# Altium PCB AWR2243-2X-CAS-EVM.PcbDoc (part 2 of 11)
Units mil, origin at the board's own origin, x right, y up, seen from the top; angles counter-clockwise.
Board outline 5118.11 x 3937.01 mil, 8 copper layers (Layer 1 - Top Layer, Layer 2 - GND, Layer 3 - Signal (Sensitive), Layer 4 - GND / Signal, Layer 5 - Signal, Layer 6 - PWR / Signal, Layer 7 - GND, Layer 8 - Bottom Layer), stack 54.8 mil thick; 629 components, 407 nets, 2243 pads, 3950 vias.
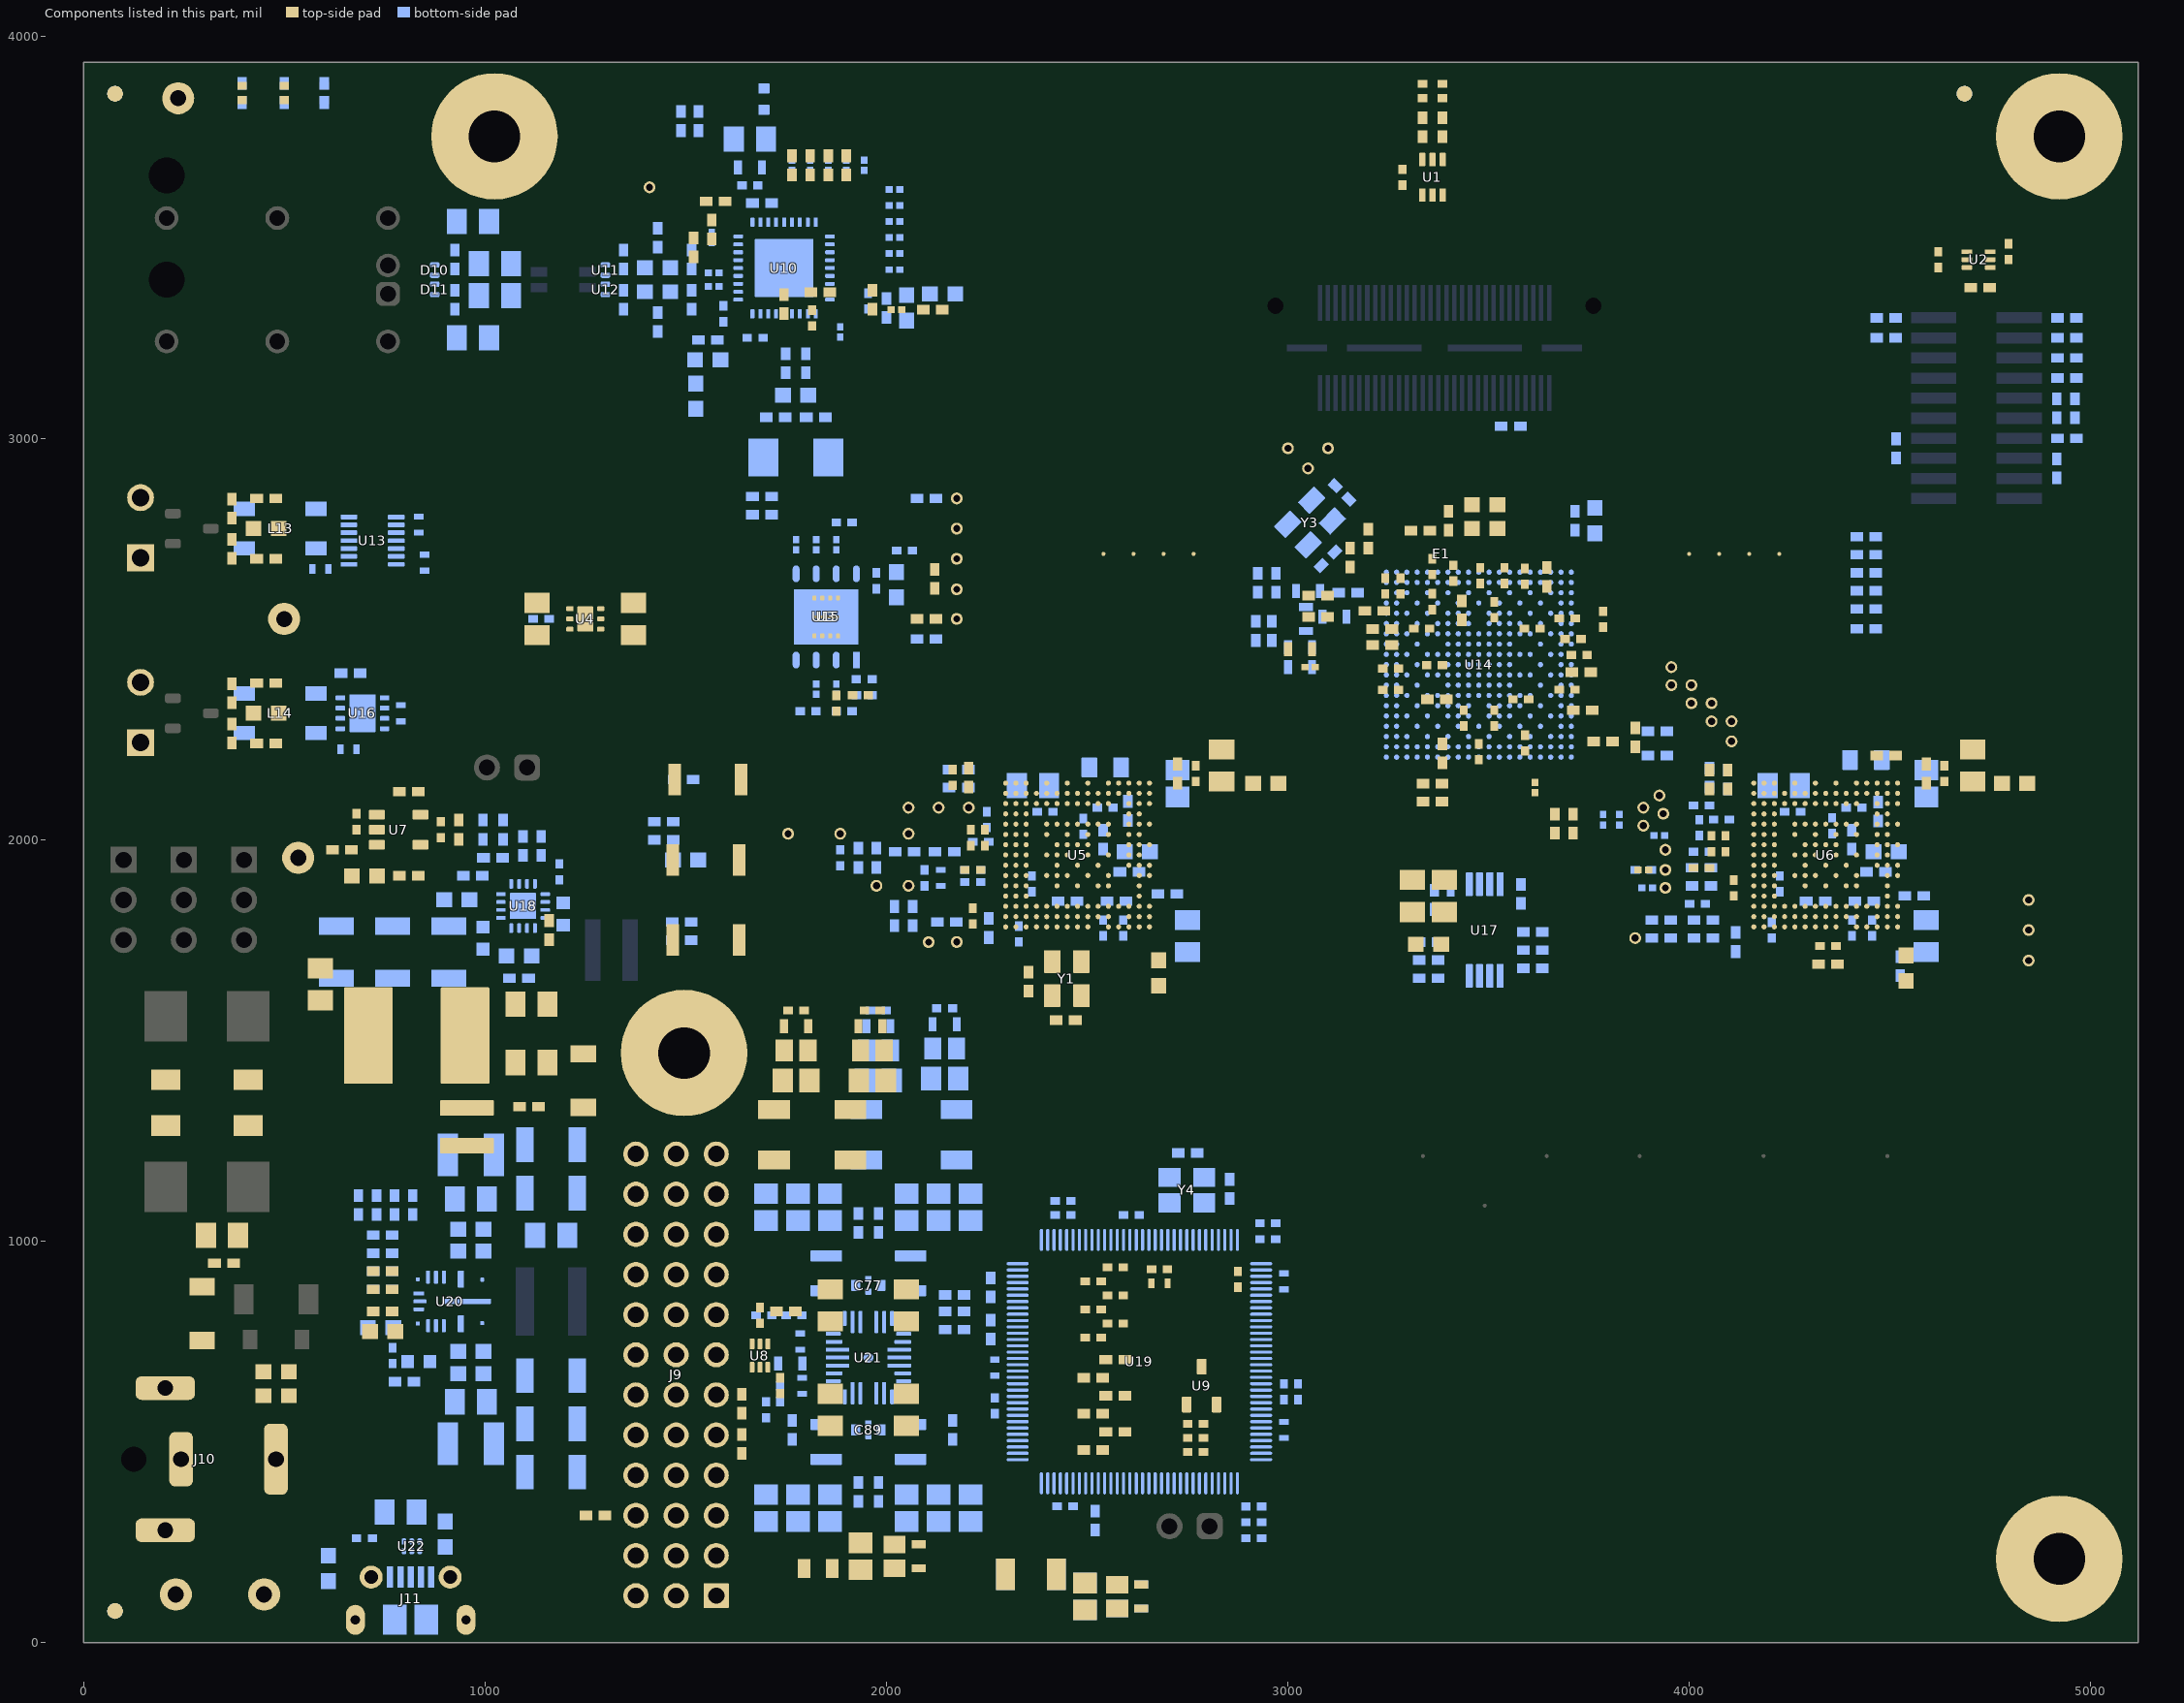
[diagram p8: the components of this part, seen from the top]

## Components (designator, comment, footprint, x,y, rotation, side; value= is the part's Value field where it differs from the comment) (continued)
R20 "CRCW040210K0JNED" 0402 3200,2750 r90 top value=10k
R21 "CRCW040210K0JNED" 0402 3330,2770 r180 top value=10k
R22 "CRCW040210K0JNED" 0402 3155,2703 r90 top value=10k
R23 "CRCW040261R9FKED" 0402 455,2700 r180 top value=61.9
R24 "CRCW040210K0FKED" 0402 3645,2655 r90 top value=10.0k
R25 "CRCW0402100KFKED" 0402 2120,2650 r90 top value=100k
R26 "CRCW040210K0DHEDP" 0402 3075,2608 r180 top value=10.0k
R27 "CRCW040210K0FKED" 0402 3215,2570 r0 top value=10.0k
R28 "CRCW040220K0FKED" 0402 3075,2555 r0 top value=20.0k
R29 "CRCW0402100KFKED" 0402 2100,2550 r180 top value=100k
R30 "CRCW040210K0FKED" 0402 3235,2525 r0 top value=10.0k
R31 "CRCW040210K0FKED" 0402 3235,2485 r180 top value=10.0k
R32 "CRCW02010000Z0ED" 0201 3055,2430 r180 top value=0
R33 "CRCW040261R9FKED" 0402 455,2390 r0 top value=61.9
R34 "CRCW040233R2FKED" 0402 3734.21,2322.69 r180 top value=33.2
R35 "CRCW040210K0FKED" 0402 3865,2255 r270 top value=10.0k
R36 "CRCW040210K0FKED" 0402 3785,2245 r0 top value=10.0k
R37 "CRCW040233R2FKED" 0402 3385,2215 r90 top value=33.2
R38 "CRCW040261R9FKED" 0402 455,2240 r180 top value=61.9
R39 "CRCW040249R9FKED" 0402 4490,2210 r180 top value=49.9
R40 "CRCW04020000Z0ED" 0402 2205,2155 r90 top value=0
R41 "CRCW04020000Z0ED" 0402 4050,2150 r90 top value=0
R42 "CRCW04022K94FKED" 0402 4095,2150 r90 top value=2.94k
R43 "CRCW04022K94FKED" 0402L 2165,2155 r90 top value=2.94k
R44 "MCT06030Z0000ZP500" 0603 2945,2140 r0 top value=0
R45 "MCT06030Z0000ZP500" 0603 4810,2140 r0 top value=0
R46 "CRCW040210K0JNED" 0402 3360,2140 r0 top value=10k
R47 "CRCW02010000Z0ED" 0201 3615,2130 r270 top value=0
R48 "CRCW040210K0JNED" 0402 3360,2095 r180 top value=10k
R49 "CRCW040210K0JNED" 0402 3665,2040 r270 top value=10k
R50 "CRCW040210K0JNED" 0402 3710,2040 r90 top value=10k
R51 "CRCW040224K9FKED" 0402 935,2025 r90 top value=24.9k
R52 "ERJ-2RKF1002X" 0402 644.25,1975 r0 top value=10.0k
R53 "CRCW040210K0FKED" 0402L 4030,1930 r180 top value=10.0k
R54 "CRCW02010000Z0ED" 0201 3885,1925 r0 top value=0
R55 "RFF" 0603 700,1910 r0 top value=1.00k
R56 "CRCW040210K0FKED" 0402L 2215,1925 r180 top value=10.0k
R57 "CRCW040260K4FKED" 0402 810,1910 r0 top value=60.4k
R58 "CRCW040210K0FKED" 0402 1160,1775 r90 top value=10.0k
R59 "CRCW040210K0FKED" 0402L 4345,1735 r0 top value=10.0k
R60 "CRCW04021R00FKED" 0402 1110,1335 r180 top value=1.00
R61 "CRCW04021R00FKED" 0402 350,945 r0 top value=1.00
R62 "CRCW040210K0FKED" 0402L 2570,935 r0 top value=10.0k
R63 "CRCW0402100KFKED" 0402 745,925 r180 top value=100k
R64 "ERJ-2GE0R00X" 0402L 2875,905 r90 top value=0
R65 "CRCW04021K00FKED" 0402L 2515,900 r180 top value=1.00k
R66 "CRCW040243K2FKED" 0402 745,880 r0 top value=43.2k
R67 "CRCW04021K00FKED" 0402L 2570,865 r180 top value=1.00k
R68 "CRCW04024K99FKED" 0402 745,825 r180 top value=4.99k
R69 "CRCW04021K00FKED" 0402L 2515,830 r0 top value=1.00k
R70 "CRCW04020000Z0ED" 0402 1750,825 r180 top value=0
R71 "CRCW04021K00FKED" 0402L 2570,795 r0 top value=1.00k
R72 "CRCW04024K87FKED" 0402L 2515,760 r180 top value=4.87k
R73 "CRCW040233R2FKED" 0402 2570,705 r180 top value=33.2
R74 "ERJ-2GE0R00X" 0402L 1735,640 r90 top value=10.0k
R75 "ERJ-2GE0R00X" 0402 2515,660 r180 top value=0
R76 "CRCW04022K94FKED" 0402 1640,595 r270 top value=2.94k
R77 "CRCW040233R2FKED" 0402 2570,615 r180 top value=33.2
R78 "CRCW040233R2FKED" 0402 2515,570 r180 top value=33.2
R79 "CRCW04021K00FKED" 0402L 2770,545 r0 top value=1.00k
R80 "ERJ-2GE0R00X" 0402 2570,525 r180 top value=0
R81 "CRCW04022K94FKED" 0402 1640,495 r90 top value=2.94k
R82 "ERJ-2GE0R00X" 0402 2515,480 r180 top value=0
R83 "CRCW04020000Z0ED" 0402 1275,316.5 r180 top value=0
R84 "ERJ-2RKF2200X" 0402 600,3860 r270 bottom value=220
R85 "ERJ-2RKF4700X" 0402 500,3860 r270 bottom value=470
R86 "ERJ-2RKF4700X" 0402 395,3860 r270 bottom value=470
R87 "CRCW04020000Z0ED" 0402 1531.77,3790 r270 bottom value=0
R88 "CRCW04020000Z0ED" 0402 1488,3790 r270 bottom value=0
R89 "CRCW020133R2FNED" 0201 1945,3680 r270 bottom value=33.2
R90 "CRCW020133R2FNED" 0201 1900,3680 r270 bottom value=33.2
R91 "CRCW020133R2FNED" 0201 1855,3680 r270 bottom value=33.2
R92 "CRCW020133R2FNED" 0201 1810,3680 r270 bottom value=33.2
R93 "CRCW020133R2FNED" 0201 1765,3680 r270 bottom value=33.2
R94 "CRCW020133R2FNED" 0201 2020,3620 r180 bottom value=33.2
R95 "CRCW020133R2FNED" 0201 2020,3580 r180 bottom value=33.2
R96 "CRCW0805100KJNEA" 0805_HV 970,3540 r180 bottom value=100k
R97 "CRCW020133R2FNED" 0201 2020,3540 r180 bottom value=33.2
R98 "CRCW020133R2FNED" 0201 1565,3500 r270 bottom value=33.2
R99 "CRCW020133R2FNED" 0201 2020,3500 r180 bottom value=33.2
R100 "CRCW040226R7FKED" 0402 1345,3445 r90 bottom value=26.7
R101 "CRCW04021K00FKED" 0402 925,3445 r270 bottom value=1.00k
R102 "CRCW020133R2FNED" 0201 2020,3460 r180 bottom value=33.2
R103 "RMCF0603ZT0R00" 0603 1430,3425 r180 bottom value=0
R104 "CRCW020133R2FNED" 0201 2020,3420 r180 bottom value=33.2
R105 "CRCW02010000Z0ED" 0201_Silk 1570,3412 r180 bottom value=0
R106 "CRCW040226R7FKED" 0402 1345,3345 r90 bottom value=26.7
R107 "CRCW04021K00FKED" 0402 925,3345 r90 bottom value=1.00k
R108 "RMCF0603ZT0R00" 0603 1430,3365 r180 bottom value=0
R109 "CRCW02010000Z0ED" 0201_Silk 1570,3378 r180 bottom value=0
R110 "CRCW04020000Z0ED" 0402 4940,3300 r0 bottom value=0
R111 "CRCW04024K70JNED" 0402 4490,3300 r0 bottom value=4.7k
R112 "CRCW020133R2FNED" 0201_Silk 1885,3265 r90 bottom value=33.2
R113 "CRCW04020000Z0ED" 0402 4940,3250 r0 bottom value=0
R114 "CRCW04020000Z0ED" 0402 4490,3250 r0 bottom value=0
R115 "CRCW04020000Z0ED" 0402 1799,3187 r90 bottom value=0
R116 "CRCW0402100RJNED" 0402 1749,3187 r270 bottom value=100
R117 "CRCW0402100RJNED" 0402 4940,3200 r0 bottom value=100
R118 "CRCW04020000Z0ED" 0402 4940,3150 r0 bottom value=0
R119 "CRCW06031M00FKEA" 0603 1774,3107 r0 bottom value=1.00Meg
R120 "CRCW04020000Z0ED" 0402 4960,3075 r90 bottom value=0
R121 "CRCW04020000Z0ED" 0402 4915,3075 r270 bottom value=0
R122 "CRCW040210K0JNED" 0402 3555,3030 r0 bottom value=10k
R123 "CRCW04024K70JNED" 0402 4515,2975 r270 bottom value=4.7k
R124 "CRCW04024K70JNED" 0402 4940,3000 r0 bottom value=4.7k
R125 "CRCW04020000Z0ED" 0402 4915,2925 r270 bottom value=0
R126 "CRCW04020000Z0ED" 0402 1690,2855 r180 bottom value=0
R127 "CRCW040210K0FKED" 0402 2100,2850 r180 bottom value=10.0k
R128 "CRCW040210K0FKED" 0402 3715,2795 r270 bottom value=10.0k
R129 "CRCW04020000Z0ED" 0402 1690,2810 r180 bottom value=0
R130 "CRCW040210K0FKED" 0402L 1895,2790 r0 bottom value=10.0k
R131 "CRCW040233R2FKED" 0402 4440,2755 r180 bottom value=33.2
R132 "CRCW020133R2FNED" 0201_Silk 1875,2735 r90 bottom value=33.2
R133 "CRCW020133R2FNED" 0201_Silk 1825,2735 r90 bottom value=33.2
R134 "CRCW020133R2FNED" 0201_Silk 1775,2735 r90 bottom value=33.2
R135 "ERJ-2GE0R00X" 0402L 2045,2720 r0 bottom value=0
R136 "CRCW040210K0FKED" 0402 4440,2710 r180 bottom value=10.0k
R137 "CRCW040220K0FKED" 0402 2970,2640 r270 bottom value=20.0k
R138 "CRCW040210K0DHEDP" 0402 2925,2640 r90 bottom value=10.0k
R139 "CRCW040233R2FKED" 0402 4440,2665 r180 bottom value=33.2
R140 "CRCW040233R2FKED" 0402 4440,2620 r180 bottom value=33.2
R141 "CRCW040210K0FKED" 0402 4440,2575 r0 bottom value=10.0k
R142 "CRCW04020000Z0ED" 0402 2960,2520 r270 bottom value=0
R143 "CRCW04020000Z0ED" 0402 2920,2520 r270 bottom value=0
R144 "CRCW040210K0FKED" 0402L 1140,2550 r0 bottom value=10.0k
R145 "CRCW040233R2FKED" 0402 4440,2525.58 r180 bottom value=33.2
R146 "CRCW040210K0JNED" 0402 2100,2500 r0 bottom value=10k
R147 "CRCW040210K0JNED" 0402 665,2415 r180 bottom value=10k
R148 "CRCW020133R2FNED" 0201_Silk 1875,2375 r90 bottom value=33.2
R149 "CRCW020133R2FNED" 0201_Silk 1825,2375 r90 bottom value=33.2
R150 "CRCW040247K5FKED" 0402L 1944.59,2400 r0 bottom value=47.5k
R151 "CRCW040210K0FKED" 0402L 1895,2320 r0 bottom value=10.0k
R152 "CRCW040210K0FKED" 0402L 1805,2320 r180 bottom value=10.0k
R153 "CRCW040233R2FKED" 0402 3920,2270 r180 bottom value=33.2
R154 "CRCW040233R2FKED" 0402 3920,2210 r180 bottom value=33.2
R155 "CRCW04022K94FKED" 0402 4095,2150 r90 bottom value=2.94k
R156 "CRCW04020000Z0ED" 0402 4050,2155 r90 bottom value=0
R157 "CRCW04022K94FKED" 0402 2180,2175 r180 bottom value=2.94k
R158 "CRCW04020000Z0ED" 0402 2180,2130 r180 bottom value=0
R159 "CRCW040210K0FKED" 0402L 4030,2085 r0 bottom value=10.0k
R160 "CRCW040210K0FKED" 0402L 2250,2050 r270 bottom value=10.0k
R161 "CRCW02010000Z0ED" 0201 3825,2050 r270 bottom value=0
R162 "CRCW02010000Z0ED" 0201 3785,2050 r270 bottom value=0
R163 "CRCW040233K0JNED" 0402 1445,2045 r180 bottom value=33k
R164 "CRCW040210K0FKED" 0402L 4025,2030 r90 bottom value=10.0k
R165 "CRCW040210K0FKED" 0402L 4080,2050 r180 bottom value=10.0k
R166 "CRCW040218K0FKED" 0402 1140,1985 r270 bottom value=18.0k
R167 "CRCW040210K0FKED" 0402 1095,1985 r270 bottom value=10.0k
R168 "CRCW02010000Z0ED" 0201 3925.23,2010.31 r0 bottom value=0
R169 "CRCW04023K30JNED" 0402 1445,2000 r180 bottom value=3.3k
R170 "CRCW040210K0FKED" 0402L 2235,1994.83 r180 bottom value=10.0k
R171 "CRCW040210K0JNED" 0402 1975,1955 r270 bottom value=10k
R172 "CRCW040210K0JNED" 0402 1930,1955 r90 bottom value=10k
R173 "CRCW040210K0JNED" 0402 2145,1970 r0 bottom value=10k
R174 "CRCW040210K0JNED" 0402 2045,1970 r0 bottom value=10k
R175 "CRCW040210K0FKED" 0402L 1885,1955 r270 bottom value=10.0k
R176 "CRCW040210K0FKED" 0402L 4030,1970 r0 bottom value=10.0k
R177 "CRCW040280K6FKED" 0402 1020,1955 r0 bottom value=80.6k
R178 "CRCW040210K0JNED" 0402 4030,1930 r180 bottom value=10k
R179 "CRCW040210K0FKED" 0402L 2095,1905 r270 bottom value=10.0k
R180 "CRCW040210K0FKED" 0402L 3885.23,1925 r180 bottom value=10.0k
R181 "CRCW040210K0FKED" 0402L 2215,1925 r180 bottom value=10.0k
R182 "CRCW04021K00FKED" 0402 970,1910 r180 bottom value=1.00k
R183 "CRCW040233R2FKED" 0402S 2135,1905 r270 bottom value=33.2
R184 "CRCW04020000Z0ED" 0402 3580,1865 r90 bottom value=0
R185 "CRCW040210K0FKED" 0402L 2215,1895 r0 bottom value=10.0k
R186 "CRCW040210K0JNED" 0402 4030,1885 r0 bottom value=10k
R187 "CRCW02010000Z0ED" 0201 3895,1880 r0 bottom value=0
R188 "CRCW040210K0JNED" 0402 2065,1810 r90 bottom value=10k
R189 "CRCW040210K0JNED" 0402 2020,1810 r270 bottom value=10k
R190 "CRCW040210K0FKED" 0402L 4020,1840 r0 bottom value=10.0k
R191 "CRCW040210K0JNED" 0402 4035,1800 r0 bottom value=10k
R192 "CRCW040210K0JNED" 0402 3930,1800 r180 bottom value=10k
R193 "CRCW04020000Z0ED" 0402 2150,1795 r180 bottom value=0
R194 "CRCW04022K49FKED" 0402 1490,1795 r180 bottom value=2.49k
R195 "CRCW04020000Z0ED" 0402 3610,1770 r180 bottom value=0
R196 "CRCW040210K0JNED" 0402 4035,1755 r180 bottom value=10k
R197 "CRCW040210K0JNED" 0402 3930,1755 r0 bottom value=10k
R198 "CRCW040249R9FKED" 0402 3350,1745 r0 bottom value=49.9
R199 "CRCW04020000Z0ED" 0402 3610,1725 r0 bottom value=0
R200 "CRCW040249R9FKED" 0402 4525,1685 r90 bottom value=49.9
R201 "CRCW04020000Z0ED" 0402 3350,1700 r180 bottom value=0
R202 "CRCW040210K0FKED" 0402 3610,1680 r0 bottom value=10.0k
R203 "CRCW04020000Z0ED" 0402 3350,1655 r180 bottom value=0
R204 "CRCW0402100KFKED" 0402 1085,1655 r0 bottom value=100k
R205 "CRCW04020000Z0ED" 0402 775,1090 r90 bottom value=0
R206 "CRCW04020000Z0ED" 0402 730,1090 r90 bottom value=0
R207 "CRCW04020000Z0ED" 0402 685,1090 r90 bottom value=0
R208 "CRCW04020000Z0ED" 0402 820,1090 r270 bottom value=0
R209 "CRCW04020000Z0ED" 0402 1980,1045 r90 bottom value=0
R210 "CRCW04020000Z0ED" 0402 1930,1045 r90 bottom value=0
R211 "CRCW040249R9FKED" 0402L 2440,1065 r0 bottom value=49.9
R212 "ERJ-2GEJ101X" 0402L 2950,1045 r0 bottom value=100
R213 "CRCW04020000Z0ED" 0402 745,1015 r0 bottom value=0
R214 "CRCW040228K0FKED" 0402 745,970 r0 bottom value=28.0k
R215 "CRCW040210K0FKED" 0402 745,925 r180 bottom value=10.0k
R216 "CRCW04020000Z0ED" 0402 2260,885 r90 bottom value=0
R217 "CRCW04026K81FKED" 0402 745,880 r0 bottom value=6.81k
R218 "CRCW04020000Z0ED" 0402 2170,825 r0 bottom value=0
R219 "CRCW04020000Z0ED" 0402 2260,780 r270 bottom value=0
R220 "CRCW04020000Z0ED" 0402L 1695,815 r180 bottom value=0
R221 "CRCW04020000Z0ED" 0402 2170,780 r0 bottom value=0
R222 "CRCW04020000Z0ED" 0402 800,650 r0 bottom value=0
R223 "CRCW04020000Z0ED" 0402L 1700,580 r270 bottom value=0
R224 "CRCW040210K0FKED" 0402 2165,530 r270 bottom value=10.0k
R225 "CRCW040210K0FKED" 0402 1765.21,530 r270 bottom value=10.0k
R226 "CRCW04020000Z0ED" 0402 1980,375 r270 bottom value=0
R227 "CRCW04020000Z0ED" 0402 1930,375 r270 bottom value=0
R228 "ERJ-2GE0R00X" 0402 2520,304.25 r90 bottom value=0
R229 "MCT06030Z0000ZP500" 0603 901,270 r90 bottom value=0
R230 "CRCW0402330KFKED" 0402L 2915,300 r180 bottom value=330k
R231 "CRCW0402330KFKED" 0402L 2915,260 r0 bottom value=330k
R232 "CRCW040230K0FKED" 0402L 700,260 r0 bottom value=30.0k
R233 "MCT06030Z0000ZP500" 0603 610,185 r90 bottom value=0
R234 "ERJ-2GE0R00X" 0402L 1945,2360 r0 bottom value=0
R235 "ERJ-2GE0R00X" 0402L 1935,2360 r0 top value=0
R236 "RMCF0603ZT0R00" 0603 2140,3360 r180 bottom value=0
R237 "RMCF0603ZT0R00" 0603 1525,3105 r90 bottom value=0
R238 "CRCW12060000Z0EAHP" 1206 410,1345 r90 top value=0
R239 "CRCW12060000Z0EAHP" 1206 205,1345 r90 top value=0
R240 "CRCW040247K5FKED" 0402L 1875,2340 r270 top value=47.5k
R241 "CRCW04021K00FKED" 0402 2170,866 r180 bottom value=1.00k
S1 "SKRKAEE010" SW_SKRKAEE010 1555,2150 r0 top
S2 "SKRKAEE010" SW_SKRKAEE010 1550,1950 r0 top
S3 "SKRKAEE010" SW_SKRKAEE010 1550,1750 r180 top
TP1 "5001" Keystone5001 235.98,3847.01 r90 top value=Black
TP2 "TP_H0.45P0.75" TP_H045P075 3000,2975 r90 top
TP3 "TP_H0.45P0.75" TP_H045P075 3100,2975 r90 top
TP4 "TP_H0.45P0.75" TP_H045P075 3050,2925 r90 top
TP5 "TP_H0.45P0.75" TP_H045P075 2175,2850 r90 top
TP6 "TP_H0.45P0.75" TP_H045P075 2175,2775 r90 top
TP7 "TP_H0.45P0.75" TP_H045P075 2175,2700 r90 top
TP8 "TP_H0.45P0.75" TP_H045P075 2175,2623.94 r90 top
TP9 "5000" Keystone5000 500,2550 r0 top value=Red
TP10 "TP_H0.45P0.75" TP_H045P075 2175,2550 r90 top
TP11 "TP_H0.45P0.75" TP_H045P075 3955,2430 r90 top
TP12 "TP_H0.45P0.75" TP_H045P075 3955,2385 r90 top
TP13 "TP_H0.45P0.75" TP_H045P075 4005,2385 r0 top
TP14 "TP_H0.45P0.75" TP_H045P075 4005,2340 r90 top
TP15 "TP_H0.45P0.75" TP_H045P075 4055,2340 r90 top
TP16 "TP_H0.45P0.75" TP_H045P075 4055,2295 r90 top
TP17 "TP_H0.45P0.75" TP_H045P075 4105,2295 r90 top
TP18 "TP_H0.45P0.75" TP_H045P075 4105,2245 r90 top
TP19 "TP_H0.45P0.75" TP_H045P075 3925.23,2110 r90 top
TP20 "TP_H0.45P0.75" TP_H045P075 2055,2080 r90 top
TP21 "TP_H0.45P0.75" TP_H045P075 2130,2080 r90 top
TP22 "TP_H0.45P0.75" TP_H045P075 2205,2080 r0 top
TP23 "TP_H0.45P0.75" TP_H045P075 3885.23,2080 r90 top
TP24 "TP_H0.45P0.75" TP_H045P075 3935,2064.76 r90 top
TP25 "TP_H0.45P0.75" TP_H045P075 3885.23,2035 r90 top
TP26 "TP_H0.45P0.75" TP_H045P075 1885,2015 r90 top
TP27 "TP_H0.45P0.75" TP_H045P075 2055,2015 r90 top
TP28 "5001" Keystone5001 535,1955 r90 top value=Black
TP29 "TP_H0.45P0.75" TP_H045P075 3940,1975 r90 top
TP30 "TP_H0.45P0.75" TP_H045P075 3940,1925 r90 top
TP31 "TP_H0.45P0.75" TP_H045P075 1975,1885.2 r90 top
TP32 "TP_H0.45P0.75" TP_H045P075 2055,1885.2 r90 top
TP33 "TP_H0.45P0.75" TP_H045P075 3940,1880 r90 top
TP34 "TP_H0.45P0.75" TP_H045P075 4845,1850 r90 top
TP35 "TP_H0.45P0.75" TP_H045P075 1755.13,2015 r90 top
TP36 "TP_H0.45P0.75" TP_H045P075 4845,1775 r90 top
TP37 "TP_H0.45P0.75" TP_H045P075 3865,1755 r90 top
TP38 "TP_H0.45P0.75" TP_H045P075 2175,1745.23 r90 top
TP39 "TP_H0.45P0.75" TP_H045P075 2105,1745 r90 top
TP40 "TP_H0.45P0.75" TP_H045P075 4845,1699.23 r90 top
TP41 "5001" Keystone5001 230,120 r90 top value=Black
TP42 "5000" Keystone5000 450,120 r90 top value=Red
TP43 "TP_H0.45P0.75" TP_H045P075 1410,3625 r90 top
U1 "SN74LVC2G17QDCKRQ1" DCK0006A_N 3360,3650 r90 top
U2 "TMP112AIDRLR" DRL0006A 4720,3445 r0 top
U3 "MX25V1635FZUS03" FP-MX25V1635FZUS03_USON8-MFG 1850,2555 r90 top
U4 "TPS7B8133QDRVRQ1" DRV0006A 1250,2550 r0 top
U5 "AWR2243ABGABLRQ1" ABL0161A 2475.98,1962.01 r270 top locked
U6 "AWR2243ABGABLRQ1" ABL0161A 4339.37,1962.01 r270 top locked
U7 "TPS78401QDBVQ1" DBV0005A_N 785,2025 r0 top
U8 "TMP112AIDRLR" DRL0006A 1685,715 r90 top
U9 "LM4040C25QDBZR" DBZ0003A_N 2785,640.28 r90 top
U10 "DP83TC812R-Q1" RHA0036A-MFG 1745,3424 r90 bottom
U11 "TPD1E10B06QDPYRQ1" DPY0002A 1300,3419 r270 bottom
U12 "TPD1E10B06QDPYRQ1" DPY0002A 1300,3371 r90 bottom
U13 "TCAN1043ADYYRQ1" DYY0014A-MFG 720,2745 r180 bottom
U14 "AM2732ADRFGQZCERQ1" ZCE0285A-MFG 3475.39,2436.14 r0 bottom locked
U15 "GD25Q64CW2G" FP-GD25Q64CW2G_WSON8-IPC_C 1850,2555 r90 bottom
U16 "TCAN1044VDRBTQ1" DRB0008J 695,2315 r180 bottom
U17 "LMK1C1102PWR" PW0008A-MFG 3490,1775 r90 bottom
U18 "TPS61379QRTE" RTE0016K-MFG 1095,1835 r180 bottom
U19 "TM4C1294NCPDTT3" PDT0128A 2630,700 r90 bottom locked
U20 "LM62460QRPHRQ1" RPH0016A 918.4,850 r90 bottom
U21 "LP876242B0RQKRQ1" RQK0032A-MFG 1955,710 r180 bottom
U22 "TPD4E004DRYR" DRY0006A 818,240 r90 bottom
Y1 "CX3225SA40000D0PTWCC" Kyocera_CX3225SA 2449.2,1654.12 r180 top
Y2 "ABM3-25.000MHZ-D2W-T" XTAL_ABM3 1774,2952 r180 bottom
Y3 "CX3225SA40000D0PTWCC" Kyocera_CX3225SA 3055,2790 r135 bottom
Y4 "NX3225SA-16.000M-STD-CRS-2" NDK_NX3225SA 2748.11,1127.01 r270 bottom
ZZ1 "This Assembly Note is for PCB labels only" AssemblyNoteLabel 225.98,4412.01 r0 top
ZZ2 "These assemblies are ESD sensitive, ESD precautions shall be observed." AssemblyNote 225.98,4312.01 r0 top
ZZ3 "These assemblies must be clean and free from flux and all contaminants. Use of no clean flux is not acceptable." AssemblyNote 225.98,4212.01 r0 top
ZZ4 "These assemblies must comply with workmanship standards IPC-A-610 Class 2, unless otherwise specified." AssemblyNote 225.98,4112.01 r0 top

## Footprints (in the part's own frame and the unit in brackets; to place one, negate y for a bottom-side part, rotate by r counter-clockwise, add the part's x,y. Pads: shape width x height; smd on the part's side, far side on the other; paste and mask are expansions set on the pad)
0201 [mm] "Data from Kemet datasheet CC101_COM dated 7/28/11"
  rect 0.46x0.42 smd mask+0.048: 1(-0.33,0) 2(0.33,0)
  body extent -0.31,-0.16 0.31,0.16, height 0.26
0201_Silk [mm] "Data from Kemet datasheet CC101_COM dated 7/28/11"
  rect 0.46x0.42 smd mask+0.048: 1(-0.33,0) 2(0.33,0)
  silkscreen extent -0.75,-0.4 0.75,0.4, body extent -0.31,-0.16 0.31,0.16, height 0.26
0402 [mm] "0402 from SM-752 data"
  rect 0.8x0.6 smd: 1(-0.6,0) 2(0.6,0)
  silkscreen extent -1.22,-0.52 1.22,0.52, body extent -0.55,-0.3 0.55,0.3, height 0.6
0402_065L [mm] "0402"
  rect 0.6x0.5 smd: 1(-0.5,0) 2(0.5,0)
  body extent -0.55,-0.3 0.55,0.3, height 0.65
0402_070 [mil] "SMD, 2-Leads, Body 1.2x0.7mm, Height 0.7mm"
  rect 15x24 smd: 1(-20,0) 2(20,0)
  body extent -24,-14 24,14, height 28
0402L [mm] "0402 from SM-752 data"
  rect 0.6x0.5 smd: 1(-0.5,0) 2(0.5,0)
  body extent -0.55,-0.3 0.55,0.3, height 0.6
0402S [mil] "Based on C0402S footprint from PADS legacy"
  rect 15x24 smd: 1(-20,0) 2(20,0)
  body extent -22,-12 22,12, height 24
0603 [mm] "0603 from SM-752 data"
  rect 1x0.95 smd: 1(-0.8,0) 2(0.8,0)
  silkscreen extent -1.52,-0.69 1.52,0.69, body extent -0.87,-0.47 0.87,0.47, height 1
0603L [mm] "0603 from SM-752 data"
  rect 0.8x0.85 smd: 1(-0.7,0) 2(0.7,0)
  silkscreen extent -0.07,-0.33 0.07,0.33, body extent -0.87,-0.47 0.87,0.47, height 1
0603S [mil]
  rect 20x35 smd: 1(-30,0) 2(30,0)
  body extent -34,-19 34,19, height 39
0805 [mm] "0805 from SM-752 data"
  rect 1.3x1.5 smd: 1(-0.85,0) 2(0.85,0)
  silkscreen extent -1.72,-0.97 1.72,0.97, body extent -1.1,-0.72 1.1,0.72, height 1.45
0805_HV [mil] "0805 with 30mil clearance between pads"
  rect 50x63 smd: 1(-40,0) 2(40,0)
  silkscreen extent -74,-40 74,40, body extent -43,-29 43,29, height 57
0805_HV1 [mm] "Custom footprint based on analyzing multiple manufacturer recommendations"
  rrect10% 1x1.25 smd: 1(-1,0) 2(1,0)
  silkscreen extent -0.2,-0.75 0.2,0.75, body extent -1.1,-0.72 1.1,0.73, height 1.45
0805L [mm] "0805 from SM-752 data"
  rect 1.1x1.4 smd: 1(-0.75,0) 2(0.75,0)
  body extent -1.1,-0.72 1.1,0.72, height 1.45
1206 [mm] "1206 from SM-752 data"
  rect 1.3x1.85 smd: 1(-1.45,0) 2(1.45,0)
  silkscreen extent -2.4,-1.21 2.4,1.21, body extent -1.7,-0.9 1.7,0.9, height 1.35
1206_180 [mm] "1206_180"
  rect 1.1x1.6 smd: 1(-1.7,0) 2(1.7,0)
  silkscreen extent -0.9,-1 0.9,1, body extent -1.75,-0.95 1.75,0.95, height 1.8
1210_270 [mm] "1210"
  rect 1.3x2.7 smd: 1(-1.45,0) 2(1.45,0)
  silkscreen extent -2.32,-1.57 2.32,1.57, body extent -1.7,-1.35 1.7,1.35, height 2.7
1210_280 [mm] "SMD, 2-Leads, Body 3.6x2.8mm, Height 2.8mm"
  rect 1.1x2.2 smd: 1(-1.65,0) 2(1.65,0)
  silkscreen extent -0.84,-1.4 0.84,1.4, body extent -1.8,-1.4 1.8,1.4, height 2.8
2220_390 [mm] "Laird recommended land pattern"
  rrect3% 3.07x6.1 smd: 1(-3.06,0) 2(3.06,0)
  silkscreen extent -1.3,-3 1.3,3, body extent -2.8,-2.54 2.79,2.54, height 3.9
ABL0161A [mm] "BGA, 161-Balls, Body 10.4x10.4mm, Pitch 0.65mm"
  round 0.32 smd mask+0.05: A1(-4.55,4.55) A2(-3.9,4.55) A3(-3.25,4.55) A5(-1.95,4.55) A7(-0.65,4.55) A9(0.65,4.55) A10(1.3,4.55) A13(3.25,4.55) A14(3.9,4.55) A15(4.55,4.55) B1(-4.55,3.9) B2(-3.9,3.9) B3(-3.25,3.9) B4(-2.6,3.9) B5(-1.95,3.9) B6(-1.3,3.9) B7(-0.65,3.9) B8(0,3.9) B9(0.65,3.9) B10(1.3,3.9) B11(1.95,3.9) B12(2.6,3.9) B13(3.25,3.9) B14(3.9,3.9) B15(4.55,3.9) C1(-4.55,3.25) C2(-3.9,3.25) C3(-3.25,3.25) C4(-2.6,3.25) C5(-1.95,3.25) C6(-1.3,3.25) C7(-0.65,3.25) C8(0,3.25) C9(0.65,3.25) C13(3.25,3.25) C14(3.9,3.25) C15(4.55,3.25) D1(-4.55,2.6) D2(-3.9,2.6) D13(3.25,2.6) D15(4.55,2.6) E1(-4.55,1.95) E2(-3.9,1.95) E3(-3.25,1.95) E5(-1.95,1.95) E6(-1.3,1.95) E8(0,1.95) E10(1.3,1.95) E11(1.95,1.95) E13(3.25,1.95) E14(3.9,1.95) E15(4.55,1.95) F2(-3.9,1.3) F3(-3.25,1.3) F5(-1.95,1.3) F9(0.65,1.3) F11(1.95,1.3) F13(3.25,1.3) F14(3.9,1.3) G1(-4.55,0.65) G2(-3.9,0.65) G3(-3.25,0.65) G5(-1.95,0.65) G6(-1.3,0.65) G7(-0.65,0.65) G8(0,0.65) G10(1.3,0.65) G13(3.25,0.65) G14(3.9,0.65) G15(4.55,0.65) H2(-3.9,0) H3(-3.25,0) H5(-1.95,0) H7(-0.65,0) H9(0.65,0) H11(1.95,0) H13(3.25,0) H14(3.9,0) H15(4.55,0) J1(-4.55,-0.65) J2(-3.9,-0.65) J3(-3.25,-0.65) J5(-1.95,-0.65) J6(-1.3,-0.65) J7(-0.65,-0.65) J8(0,-0.65) J10(1.3,-0.65) J13(3.25,-0.65) J14(3.9,-0.65) J15(4.55,-0.65) K2(-3.9,-1.3) K3(-3.25,-1.3) K5(-1.95,-1.3) K7(-0.65,-1.3) K8(0,-1.3) K9(0.65,-1.3) K10(1.3,-1.3) K11(1.95,-1.3) K13(3.25,-1.3) K14(3.9,-1.3) K15(4.55,-1.3) L1(-4.55,-1.95) L2(-3.9,-1.95) L3(-3.25,-1.95) L5(-1.95,-1.95) L6(-1.3,-1.95) L8(0,-1.95) L10(1.3,-1.95) L13(3.25,-1.95) L14(3.9,-1.95) L15(4.55,-1.95) M2(-3.9,-2.6) M3(-3.25,-2.6) M13(3.25,-2.6) M14(3.9,-2.6) M15(4.55,-2.6) N1(-4.55,-3.25) N2(-3.9,-3.25) N3(-3.25,-3.25) N4(-2.6,-3.25) N5(-1.95,-3.25) N6(-1.3,-3.25) N7(-0.65,-3.25) N8(0,-3.25) N9(0.65,-3.25) N10(1.3,-3.25) N11(1.95,-3.25) N12(2.6,-3.25) N13(3.25,-3.25) N14(3.9,-3.25) N15(4.55,-3.25) P1(-4.55,-3.9) P2(-3.9,-3.9) P3(-3.25,-3.9) P4(-2.6,-3.9) P5(-1.95,-3.9) P6(-1.3,-3.9) P7(-0.65,-3.9) P8(0,-3.9) P9(0.65,-3.9) P10(1.3,-3.9) P11(1.95,-3.9) P12(2.6,-3.9) P13(3.25,-3.9) P14(3.9,-3.9) P15(4.55,-3.9) R1(-4.55,-4.55) R2(-3.9,-4.55) R3(-3.25,-4.55) R4(-2.6,-4.55) R5(-1.95,-4.55) R6(-1.3,-4.55) R7(-0.65,-4.55) R8(0,-4.55) R9(0.65,-4.55) R10(1.3,-4.55) R11(1.95,-4.55) R12(2.6,-4.55) R13(3.25,-4.55) R14(3.9,-4.55) R15(4.55,-4.55)
  silkscreen extent -5.3,-5.3 5.3,5.3, body extent -5.2,-5.2 5.2,5.2, height 0.62
ACT45B [mm] "SMD, 4-Leads, Body 4.7 x 3.7 mm"
  rect 1.35x0.9 smd: 1(-2.275,1.25) 2(-2.275,-1.25) 3(2.275,-1.25) 4(2.275,1.25)
  silkscreen extent -2.35,-1.7 2.35,2, body extent -2.35,-1.7 2.35,1.7, height 3
AssemblyNote [mil] "Assembly Note"
AssemblyNoteLabel [mil] "Assembly Note for PCB Labels"
CE_Mark_5mm [mil] "Minimum text height for CE Mark"
  silkscreen extent -138,-98 138,98
CONN_105017-0001 [mm] "Molex Micro USB-B"
  rect 0.4x1.35 smd: 1(-1.3,1.35) 2(-0.65,1.35) 3(0,1.35) 4(0.65,1.35) 5(1.3,1.35)
  oval 1.2x1.9 hole 0.6 slot 1.3 at 90 deg: 6(-3.5,-1.35) 9(3.5,-1.35)
  rect 1.5x1.9 smd: 7(-1,-1.35) 8(1,-1.35)
  round 1.45 hole 0.85: 10(2.5,1.35) 11(-2.5,1.35)
  Layer 1 - Top Layer region: 3.5,-2.3 2.3,-2.3 2.3,-0.4 3.5,-0.4
  Layer 1 - Top Layer region: -3.5,-0.4 -2.3,-0.4 -2.3,-2.3 -3.5,-2.3
  silkscreen extent -4.1,-0.2 4.1,1.4, body extent -4.1,-3.93 4.1,1.5, height 2.72
CUI_PJ-063AH [mm] "DC POWER JACK, R/A, TH"
  rrect50% 1.5x4.5 hole 1 square: 1(-4.5,0)
  rrect50% 1.5x3.45 hole 1 square: 2(1.5,0)
  oval 1.35x1.3 hole 1.6 unplated mask+0.102: ALIGN(4.5,0)
  rrect50% 3.75x1.5 hole 1 square: S1(2.5,-4.5) S2(2.5,4.5)
  body extent -5.5,-5.15 7.5,5.15, height 9
DBV0005A_N [mm] "SOT23, 5-Leads, Body 2.9x1.6mm, Pitch 0.95mm, Lead Span 2.8mm, IPC Medium Density"
  rrect17% 1x0.6 smd: 1(-1.375,0.95) 2(-1.375,0) 3(-1.375,-0.95) 4(1.375,-0.95) 5(1.375,0.95)
  silkscreen extent -1.63,-1.55 0.38,1.55, body extent -1.42,-1.46 1.42,1.46, height 1.09
DBZ0003A_N [mm] "SOT23, 3-Leads, Body 2.9x1.3mm, Pitch 0.95mm, Lead Span 2.4mm, IPC Medium Density"
  rrect17% 1x0.6 smd: 1(-1.2,0.95) 2(-1.2,-0.95) 3(1.2,0)
  silkscreen extent 0.2,-1.5 0.7,1.5, body extent -1.26,-1.46 1.26,1.46, height 0.98
DCK0006A_N [mm] "SOT23, 6-Leads, Body 2x1.3mm, Pitch 0.65mm, Lead Span 2.1mm, IPC Medium Density"
  rrect25% 0.85x0.4 smd: 1(-1.125,0.65) 2(-1.125,0) 3(-1.125,-0.65) 4(1.125,-0.65) 5(1.125,0) 6(1.125,0.65)
  silkscreen extent -1.5,-1.09 0.51,1.09, body extent -1.14,-1 1.14,1, height 0.95
DPY0002A [mm] "X1SON-2"
  rrect57% 0.35x0.6 smd paste-0.5 mask-0.05: 1(-0.325,0) 2(0.325,0)
  rrect33% 0.3x0.5 on Bottom Paste: 1S(-0.35,0) 2S(0.35,0)
  silkscreen extent -0.38,-0.66 -0.33,-0.61, body extent -0.5,-0.3 0.5,0.3, height 0.45
DRB0008J [mm] "VSON-8"
  rrect33% 0.6x0.31 smd: 1(-1.4,0.975) 2(-1.4,0.325) 3(-1.4,-0.325) 4(-1.4,-0.975) 5(1.4,-0.975) 6(1.4,-0.325) 7(1.4,0.325) 8(1.4,0.975)
  rrect6% 1.65x2.4 smd paste-1.2: 9(0,0)
  silkscreen extent -1.73,-1.73 1.73,1.73, body extent -1.55,-1.55 1.55,1.55, height 1.01
DRL0006A [mm] "SOTFL, 6-Flat Leads, Body 1.2x1.6x0.6mm, Pitch 0.5mm, TI recommended"
  rrect33% 0.67x0.3 smd: 1(-0.74,0.5) 2(-0.74,0) 3(-0.74,-0.5) 4(0.74,-0.5) 5(0.74,0) 6(0.74,0.5)
  silkscreen extent -0.9,-0.95 0.5,0.95, body extent -0.8,-0.8 0.8,0.8, height 0.61
DRV0006A [mm] "SON, 6-Leads, Body 2x2mm, Pitch 0.65mm, Thermal Pad 1.6x1mm, TI Recommended"
  rrect33% 0.45x0.3 smd: 1(-0.975,0.65) 2(-0.975,0) 3(-0.975,-0.65) 4(0.975,-0.65) 5(0.975,0) 6(0.975,0.65)
  rrect14% 1x0.7 on Top Paste: 7(0,-0.45) 7(0,0.45)
  rrect10% 1x1.6 smd paste-0.5: 7(0,0)
  silkscreen extent -1.05,-1.2 1.05,1.2, body extent -1.05,-1.05 1.05,1.05, height 0.81
DRY0006A [mm] "USON-6"
  rrect67% 0.45x0.3 smd paste-0.05 mask-0.05: 1(-0.275,0.5)
  rrect67% 0.4x0.3 smd paste-0.05 mask-0.05: 2(-0.3,0) 3(-0.3,-0.5) 4(0.3,-0.5) 5(0.3,0) 6(0.3,0.5)
  body extent -0.5,-0.72 0.5,0.72, height 0.58
DYY0014A-MFG [mm]
  rrect33% 1.05x0.3 smd paste+0 mask+0: 1(-1.5,1.5) 2(-1.5,1) 3(-1.5,0.5) 4(-1.5,0) 5(-1.5,-0.5) 6(-1.5,-1) 7(-1.5,-1.5) 8(1.5,-1.5) 9(1.5,-1) 10(1.5,-0.5) 11(1.5,0) 12(1.5,0.5) 13(1.5,1) 14(1.5,1.5)
  silkscreen extent -1.9,-2.15 1.05,2.28, body extent -1.63,-2.1 1.63,2.1, height 1.1
ESD_Overlay_Small [mil]
  silkscreen extent -62,-48 64,61
FCC_disclaimer [mil]
Fiducial10-20 [mm]
  round 1 smd mask+0.5: 1(0,0)
FP-1902D_HEX_STANDOFF_#4-40-MFG [mil]
  round 128.5 hole 128.5 unplated paste-39370.1 mask+0: ""(0,0)
  body extent -125,-144 125,144, height 765
"FP-BLM18KG601SH1_0603 (1608 Metric)-MFG" [mm]
  rrect15% 0.65x0.7 smd paste+0 mask+0: 1(-0.675,0) 2(0.675,0)
  silkscreen extent -0.87,-0.75 0.87,0.75, body extent -0.8,-0.4 0.8,0.4, height 0.95
FP-GD25Q64CW2G_WSON8-IPC_C [mm]
  rrect23% 1.059x0.436 smd paste+0 mask+0: 1(-2.727,1.905)
  rrect100% 1.059x0.436 smd paste+0 mask+0: 2(-2.727,0.635) 3(-2.727,-0.635) 4(-2.727,-1.905) 5(2.727,-1.905) 6(2.727,-0.635) 7(2.727,0.635) 8(2.727,1.905)
  rrect3% 3.5x4.1 smd paste-1000 mask+0: 9(0,0)
  silkscreen extent -3,-2.5 3,3.17, body extent -3,-2.5 3,2.5, height 0.81
FP-MX25V1635FZUS03_USON8-MFG [mm]
  rrect40% 0.3x0.25 smd paste+0 mask+0: 1(-1.2,0.75) 2(-1.2,0.25) 3(-1.2,-0.25) 4(-1.2,-0.75) 5(1.2,-0.75) 6(1.2,-0.25) 7(1.2,0.25) 8(1.2,0.75)
  rrect50% 0.2x1.6 smd paste+0 mask+0: 9(0,0)
  silkscreen extent -2.12,-1.25 1.55,1.25, body extent -1.5,-1 1.5,1, height 0.6
FP-NFM18HC105C1C3D_0603-MFG [mm]
  rrect17% 0.6x0.7 smd paste+0 mask+0: 1(-0.8,0) 3(0.8,0)
  rrect25% 0.4x0.4 smd paste+0 mask+0: 2(0,-0.4) 2(0,0.4)
  silkscreen extent -1.27,-1.01 0.85,0.97, body extent -0.8,-0.4 0.8,0.4, height 0.7
FP-SSW-112-01-L-T_HDR36-MFG [mm]
  rrect6% 1.59x1.59 hole 1.04 paste-1000 mask+0: 1(13.97,-2.54)
  round 1.59 hole 1.04 paste-1000 mask+0: 2(13.97,0) 3(13.97,2.54) 4(11.43,-2.54) 5(11.43,0) 6(11.43,2.54) 7(8.89,-2.54) 8(8.89,0) 9(8.89,2.54) 10(6.35,-2.54) 11(6.35,0) 12(6.35,2.54) 13(3.81,-2.54) 14(3.81,0) 15(3.81,2.54) 16(1.27,-2.54) 17(1.27,0) 18(1.27,2.54) 19(-1.27,-2.54) 20(-1.27,0) 21(-1.27,2.54) 22(-3.81,-2.54) 23(-3.81,0) 24(-3.81,2.54) 25(-6.35,-2.54) 26(-6.35,0) 27(-6.35,2.54) 28(-8.89,-2.54) 29(-8.89,0) 30(-8.89,2.54) 31(-11.43,-2.54) 32(-11.43,0) 33(-11.43,2.54) 34(-13.97,-2.54) 35(-13.97,0) 36(-13.97,2.54)
  silkscreen extent -15.62,-4.59 15.62,3.81, body extent -15.49,-3.75 15.49,3.75, height 8.64
FP-TFM252012ALMAR47MTAA_1008-MFG [mm]
  rrect14% 0.7x2 smd paste+0 mask+0: 1(-1.1,0) 2(1.1,0)
  silkscreen extent -0.38,-1.1 0.38,1.1, body extent -1.25,-1 1.25,1, height 1.2
FP-XGL4030-102MEC_SMD_IND_4MM0_4MM0-MFG [mm]
  rrect10% 0.98x3.4 smd paste+0 mask+0: 1(-1.185,0) 2(1.185,0)
  silkscreen extent -2.15,-2.15 2.15,2.15, body extent -2.25,-2.25 2.25,2.25, height 0.25
IEC_HotSurface_Small [mil]
  silkscreen extent -107,-93 107,92
Keystone5000 [mil] "For Keystone 500x miniature loop terminals"
  round 80 hole 40: 1(0,0)
  silkscreen extent -52,-52 52,52, body extent -49,-49 49,49, height 182
Keystone5001 [mil] "For Keystone 500x miniature loop terminals"
  round 80 hole 40: 1(0,0)
  silkscreen extent -52,-52 52,52, body extent -49,-49 49,49, height 182
Kyocera_CX3225SA [mm] "SMD, 4-Leads, Body 3.2x2.5mm"
  rrect10% 1.05x1.45 smd: 1(-0.925,1.075) 2(-0.925,-1.075) 3(0.925,-1.075) 4(0.925,1.075)
  silkscreen extent -1.48,2.07 -1.36,2.2, body extent -1.3,-1.65 1.3,1.65, height 0.9
Label_650x200 [mil] "Thermal Transfer Label"
  round 1 on Mech13: 0(0,0)
  silkscreen extent -325,-100 325,100, body extent -325,-100 325,100, height 1
LED_SMLP12_ORANGE [mm] "Rohm Semiconductor"
  rect 0.5x0.6 smd mask+0.08: 1(-0.45,0) 2(0.45,0)
  silkscreen extent 0.92,-0.3 0.92,0.3, body extent -0.55,-0.35 0.55,0.35, height 0.25
LED_SMLP12_YELLOW [mm] "Rohm Semiconductor"
  rect 0.5x0.6 smd mask+0.08: 1(-0.45,0) 2(0.45,0)
  silkscreen extent 0.92,-0.3 0.92,0.3, body extent -0.55,-0.35 0.55,0.35, height 0.25
MPZ2012 [mm] "TDK"
  rect 0.8x1.2 smd: 1(-0.9,0) 2(0.9,0)
  body extent -1.1,-0.72 1.1,0.72, height 1.05
NDK_NX3225SA [mm] "NDK"
  rect 1.2x1.4 smd: 1(-0.8,1.1) 2(-0.8,-1.1) 3(0.8,-1.1) 4(0.8,1.1)
  body extent -1.3,-1.65 1.3,1.65, height 0.7
NLCV32 [mm] "TDK"
  rect 1.2x2 smd: 1(-1.6,0) 2(1.6,0)
  silkscreen extent -0.9,-1.4 0.9,1.4, body extent -1.7,-1.35 1.7,1.35, height 2.4
"NY PMS 440 0025 PH" [mm] "4-40 nylon screw and mounting hole"
  round 8 hole 3.2: 1(0,0)
  body extent -3.3,-3.3 3.3,3.3, height 2.69
PDT0128A [mm] "Thin QFP, 128-Leads, Body 14x14mm, Pitch 0.4mm"
  oval 1.4x0.2 smd: 1(-7.7,6.2) 2(-7.7,5.8) 3(-7.7,5.4) 4(-7.7,5) 5(-7.7,4.6) 6(-7.7,4.2) 7(-7.7,3.8) 8(-7.7,3.4) 9(-7.7,3) 10(-7.7,2.6) 11(-7.7,2.2) 12(-7.7,1.8) 13(-7.7,1.4) 14(-7.7,1) 15(-7.7,0.6) 16(-7.7,0.2) 17(-7.7,-0.2) 18(-7.7,-0.6) 19(-7.7,-1) 20(-7.7,-1.4) 21(-7.7,-1.8) 22(-7.7,-2.2) 23(-7.7,-2.6) 24(-7.7,-3) 25(-7.7,-3.4) 26(-7.7,-3.8) 27(-7.7,-4.2) 28(-7.7,-4.6) 29(-7.7,-5) 30(-7.7,-5.4) 31(-7.7,-5.8) 32(-7.7,-6.2) 65(7.7,-6.2) 66(7.7,-5.8) 67(7.7,-5.4) 68(7.7,-5) 69(7.7,-4.6) 70(7.7,-4.2) 71(7.7,-3.8) 72(7.7,-3.4) 73(7.7,-3) 74(7.7,-2.6) 75(7.7,-2.2) 76(7.7,-1.8) 77(7.7,-1.4) 78(7.7,-1) 79(7.7,-0.6) 80(7.7,-0.2) 81(7.7,0.2) 82(7.7,0.6) 83(7.7,1) 84(7.7,1.4) 85(7.7,1.8) 86(7.7,2.2) 87(7.7,2.6) 88(7.7,3) 89(7.7,3.4) 90(7.7,3.8) 91(7.7,4.2) 92(7.7,4.6) 93(7.7,5) 94(7.7,5.4) 95(7.7,5.8) 96(7.7,6.2)
  oval 0.2x1.4 smd: 33(-6.2,-7.7) 34(-5.8,-7.7) 35(-5.4,-7.7) 36(-5,-7.7) 37(-4.6,-7.7) 38(-4.2,-7.7) 39(-3.8,-7.7) 40(-3.4,-7.7) 41(-3,-7.7) 42(-2.6,-7.7) 43(-2.2,-7.7) 44(-1.8,-7.7) 45(-1.4,-7.7) 46(-1,-7.7) 47(-0.6,-7.7) 48(-0.2,-7.7) 49(0.2,-7.7) 50(0.6,-7.7) 51(1,-7.7) 52(1.4,-7.7) 53(1.8,-7.7) 54(2.2,-7.7) 55(2.6,-7.7) 56(3,-7.7) 57(3.4,-7.7) 58(3.8,-7.7) 59(4.2,-7.7) 60(4.6,-7.7) 61(5,-7.7) 62(5.4,-7.7) 63(5.8,-7.7) 64(6.2,-7.7) 97(6.2,7.7) 98(5.8,7.7) 99(5.4,7.7) 100(5,7.7) 101(4.6,7.7) 102(4.2,7.7) 103(3.8,7.7) 104(3.4,7.7) 105(3,7.7) 106(2.6,7.7) 107(2.2,7.7) 108(1.8,7.7) 109(1.4,7.7) 110(1,7.7) 111(0.6,7.7) 112(0.2,7.7) 113(-0.2,7.7) 114(-0.6,7.7) 115(-1,7.7) 116(-1.4,7.7) 117(-1.8,7.7) 118(-2.2,7.7) 119(-2.6,7.7) 120(-3,7.7) 121(-3.4,7.7) 122(-3.8,7.7) 123(-4.2,7.7) 124(-4.6,7.7) 125(-5,7.7) 126(-5.4,7.7) 127(-5.8,7.7) 128(-6.2,7.7)
  silkscreen extent -7.7,-6.3 6.3,7, body extent -8,-8 8,8, height 1.07
PhoenixConact_1727010 [mm]
  rect 1.7x1.7 hole 1.1: 1(-1.905,0)
  round 1.7 hole 1.1: 2(1.905,0)
  silkscreen extent -4.8,-3.6 3.81,3.6, body extent -3.81,-3.6 3.81,3.7, height 8.52
PW0008A-MFG [mm]
  rrect22% 1.5x0.45 smd paste+0 mask+0: 1(-2.9,0.975) 2(-2.9,0.325) 3(-2.9,-0.325) 4(-2.9,-0.975) 5(2.9,-0.975) 6(2.9,-0.325) 7(2.9,0.325) 8(2.9,0.975)
  silkscreen extent -4.37,-1.55 1.77,1.55, body extent -3.2,-1.5 3.2,1.5, height 1.2
RHA0036A-MFG [mm]
  rrect40% 0.6x0.25 smd paste+0 mask+0: 1(-2.9,2) 2(-2.9,1.5) 3(-2.9,1) 4(-2.9,0.5) 5(-2.9,0) 6(-2.9,-0.5) 7(-2.9,-1) 8(-2.9,-1.5) 9(-2.9,-2) 19(2.9,-2) 20(2.9,-1.5) 21(2.9,-1) 22(2.9,-0.5) 23(2.9,0) 24(2.9,0.5) 25(2.9,1) 26(2.9,1.5) 27(2.9,2)
  rrect40% 0.25x0.6 smd paste+0 mask+0: 10(-2,-2.9) 11(-1.5,-2.9) 12(-1,-2.9) 13(-0.5,-2.9) 14(0,-2.9) 15(0.5,-2.9) 16(1,-2.9) 17(1.5,-2.9) 18(2,-2.9) 28(2,2.9) 29(1.5,2.9) 30(1,2.9) 31(0.5,2.9) 32(0,2.9) 33(-0.5,2.9) 34(-1,2.9) 35(-1.5,2.9) 36(-2,2.9)
  rrect3% 3.7x3.7 smd paste-1000 mask+0: 37(0,0)
  silkscreen extent -4.12,-3.05 3.05,3.05, body extent -3,-3 3,3, height 0.95
RPH0016A [mm] "QFN, 16-Leads, Body 3.5x4.5mm"
  rrect40% 0.25x0.25 smd paste-0.25: 1(-1.375,1.9) 6(-1.4,-2.175) 10(1.4,-2.175) 15(1.375,1.9)
  rrect25% 1.075x0.4 smd: 2(-1.413,0.55) 14(1.413,0.55)
  rrect40% 0.825x0.25 smd: 3(-1.538,-0.525) 4(-1.538,-1.025) 5(-1.538,-1.525) 11(1.538,-1.525) 12(1.538,-1.025) 13(1.538,-0.525)
  rrect40% 0.25x0.675 smd: 7(-0.5,-2.113) 9(0.5,-2.113)
  rrect40% 0.25x0.825 smd: 8(0,-2.038)
  rrect29% 0.35x2.975 smd: 16(0,0.963)
  Layer 1 - Top Layer region: 1.95,-2.05 1.946,-2.069 1.935,-2.085 1.919,-2.096 1.9,-2.1 1.9,-2.1 1.65,-2.1 1.631,-2.104 1.615,-2.115 1.604,-2.131 1.6,-2.15 1.6,-2.15 1.6,-2.4 1.596,-2.419 1.585,-2.435 1.569,-2.446 1.55,-2.45 1.55,-2.45 0.9,-2.45 0.881,-2.446 0.865,-2.435 0.854,-2.419 0.85,-2.4 0.85,-2.4 0.85,-1.95 0.854,-1.931 0.865,-1.915 0.881,-1.904 0.9,-1.9 0.9,-1.9 1.9,-1.9 1.919,-1.904 1.935,-1.915 1.946,-1.931 1.95,-1.95 1.95,-1.95
  Layer 1 - Top Layer region: -1.95,-2.05 -1.946,-2.069 -1.935,-2.085 -1.919,-2.096 -1.9,-2.1 -1.9,-2.1 -1.65,-2.1 -1.631,-2.104 -1.615,-2.115 -1.604,-2.131 -1.6,-2.15 -1.6,-2.15 -1.6,-2.4 -1.596,-2.419 -1.585,-2.435 -1.569,-2.446 -1.55,-2.45 -1.55,-2.45 -0.9,-2.45 -0.881,-2.446 -0.865,-2.435 -0.854,-2.419 -0.85,-2.4 -0.85,-2.4 -0.85,-1.95 -0.854,-1.931 -0.865,-1.915 -0.881,-1.904 -0.9,-1.9 -0.9,-1.9 -1.9,-1.9 -1.919,-1.904 -1.935,-1.915 -1.946,-1.931 -1.95,-1.95 -1.95,-1.95
  Layer 1 - Top Layer region: -1.95,1.4 -1.95,2.05 -1.946,2.069 -1.935,2.085 -1.919,2.096 -1.9,2.1 -1.9,2.1 -1.65,2.1 -1.631,2.104 -1.615,2.115 -1.604,2.131 -1.6,2.15 -1.6,2.15 -1.6,2.4 -1.596,2.419 -1.585,2.435 -1.569,2.446 -1.55,2.45 -1.55,2.45 -0.85,2.45 -0.831,2.446 -0.815,2.435 -0.804,2.419 -0.8,2.4 -0.8,2.4 -0.8,1.4 -0.804,1.381 -0.815,1.365 -0.831,1.354 -0.85,1.35 -0.85,1.35 -1.9,1.35 -1.919,1.354 -1.935,1.365 -1.946,1.381 -1.95,1.4
  Layer 1 - Top Layer region: 1.95,1.4 1.95,2.05 1.946,2.069 1.935,2.085 1.919,2.096 1.9,2.1 1.9,2.1 1.65,2.1 1.631,2.104 1.615,2.115 1.604,2.131 1.6,2.15 1.6,2.15 1.6,2.4 1.596,2.419 1.585,2.435 1.569,2.446 1.55,2.45 1.55,2.45 0.85,2.45 0.831,2.446 0.815,2.435 0.804,2.419 0.8,2.4 0.8,2.4 0.8,1.4 0.804,1.381 0.815,1.365 0.831,1.354 0.85,1.35 0.85,1.35 1.9,1.35 1.919,1.354 1.935,1.365 1.946,1.381 1.95,1.4
  body extent -1.8,-2.3 1.8,2.3, height 1
RQK0032A-MFG [mm]
  round 0.371 smd paste-1000 mask+0: 1(-2.081,2.081) 25(2.081,2.081)
  rrect40% 0.95x0.25 smd paste+0 mask+0: 2(-2.225,1.5) 8(-2.225,-1.5) 18(2.225,-1.5) 24(2.225,1.5)
  rrect40% 1.05x0.25 smd paste+0 mask+0: 3(-2.175,1) 7(-2.175,-1) 19(2.175,-1) 23(2.175,1)
  rrect40% 1.5x0.25 smd paste+0 mask+0: 4(-1.95,0.5) 5(-1.95,0) 6(-1.95,-0.5) 20(1.95,-0.5) 21(1.95,0) 22(1.95,0.5)
  round 0.357 smd paste-1000 mask+0: 9(-2.133,-2.073) 17(2.133,-2.073)
  rrect40% 0.25x0.95 smd paste+0 mask+0: 10(-1.5,-2.475) 16(1.5,-2.475) 26(1.5,2.475) 32(-1.5,2.475)
  rrect40% 0.25x1.4 smd paste+0 mask+0: 11(-1,-2.25) 12(-0.5,-2.25) 14(0.5,-2.25) 15(1,-2.25) 27(1,2.25) 28(0.5,2.25) 30(-0.5,2.25) 31(-1,2.25)
  round 0.63 smd paste-1000 mask+0: 13(0,0)
  Layer 1 - Top Layer region: 2.65,1.875 2.669,1.879 2.685,1.89 2.696,1.906 2.7,1.925 2.7,1.925 2.7,2.225 2.693,2.25 2.675,2.268 2.65,2.275 2.65,2.275 2.25,2.275 2.25,2.9 2.243,2.925 2.225,2.943 2.2,2.95 2.2,2.95 1.925,2.95 1.9,2.943 1.882,2.925 1.875,2.9 1.875,2.9 1.875,1.925 1.879,1.906 1.89,1.89 1.906,1.879 1.925,1.875 1.925,1.875
  Layer 1 - Top Layer region: 2.65,-1.875 2.669,-1.879 2.685,-1.89 2.696,-1.906 2.7,-1.925 2.7,-1.925 2.7,-2.225 2.693,-2.25 2.675,-2.268 2.65,-2.275 2.65,-2.275 2.25,-2.275 2.25,-2.9 2.243,-2.925 2.225,-2.943 2.2,-2.95 2.2,-2.95 1.925,-2.95 1.9,-2.943 1.882,-2.925 1.875,-2.9 1.875,-2.9 1.875,-1.925 1.879,-1.906 1.89,-1.89 1.906,-1.879 1.925,-1.875 1.925,-1.875
  Layer 1 - Top Layer region: -2.65,-1.875 -2.669,-1.879 -2.685,-1.89 -2.696,-1.906 -2.7,-1.925 -2.7,-1.925 -2.7,-2.225 -2.693,-2.25 -2.675,-2.268 -2.65,-2.275 -2.65,-2.275 -2.25,-2.275 -2.25,-2.9 -2.243,-2.925 -2.225,-2.943 -2.2,-2.95 -2.2,-2.95 -1.925,-2.95 -1.9,-2.943 -1.882,-2.925 -1.875,-2.9 -1.875,-2.9 -1.875,-1.925 -1.879,-1.906 -1.89,-1.89 -1.906,-1.879 -1.925,-1.875 -1.925,-1.875
  Layer 1 - Top Layer region: -2.65,1.875 -2.669,1.879 -2.685,1.89 -2.696,1.906 -2.7,1.925 -2.7,1.925 -2.7,2.225 -2.693,2.25 -2.675,2.268 -2.65,2.275 -2.65,2.275 -2.25,2.275 -2.25,2.9 -2.243,2.925 -2.225,2.943 -2.2,2.95 -2.2,2.95 -1.925,2.95 -1.9,2.943 -1.882,2.925 -1.875,2.9 -1.875,2.9 -1.875,1.925 -1.879,1.906 -1.89,1.89 -1.906,1.879 -1.925,1.875 -1.925,1.875
  Layer 1 - Top Layer region: -0.075,-2.95 -0.1,-2.943 -0.118,-2.925 -0.125,-2.9 -0.125,-2.9 -0.125,-1.1 -0.3,-1.1 -0.325,-1.093 -0.343,-1.075 -0.35,-1.05 -0.35,-1.05 -0.35,1.05 -0.343,1.075 -0.325,1.093 -0.3,1.1 -0.3,1.1 -0.125,1.1 -0.125,2.9 -0.118,2.925 -0.1,2.943 -0.075,2.95 -0.075,2.95 0.075,2.95 0.1,2.943 0.118,2.925 0.125,2.9 0.125,2.9 0.125,1.1 0.3,1.1 0.325,1.093 0.343,1.075 0.35,1.05 0.35,1.05 0.35,-1.05 0.343,-1.075 0.325,-1.093 0.3,-1.1 0.3,-1.1 0.125,-1.1 0.125,-2.9 0.118,-2.925 0.1,-2.943 0.075,-2.95 0.075,-2.95
  silkscreen extent -3.38,-3.35 2.55,3.35, body extent -2.5,-2.75 2.5,2.75, height 1
RTE0016K-MFG [mm]
  rrect42% 0.6x0.24 smd paste+0 mask+0: 1(-1.4,0.75) 2(-1.4,0.25) 3(-1.4,-0.25) 4(-1.4,-0.75) 9(1.4,-0.75) 10(1.4,-0.25) 11(1.4,0.25) 12(1.4,0.75)
  rrect42% 0.24x0.6 smd paste+0 mask+0: 5(-0.75,-1.4) 6(-0.25,-1.4) 7(0.25,-1.4) 8(0.75,-1.4) 13(0.75,1.4) 14(0.25,1.4) 15(-0.25,1.4) 16(-0.75,1.4)
  rrect6% 1.66x1.66 smd paste-1000 mask+0: 17(0,0)
  silkscreen extent -2.34,-1.58 1.58,1.58, body extent -1.5,-1.5 1.5,1.5, height 0.8
"RX Antenna" [mm] "RX 80 Ghz Antenna"
  round 0.25 smd: "D1 - RX1"(0.139,0.25) "D1 - RX2"(2.039,0.25) "D1 - RX3"(3.939,0.25) "D1 - RX4"(5.839,0.25) "D2 - RX1"(37.189,0.25) "D2 - RX2"(39.089,0.25) "D2 - RX3"(40.989,0.25) "D2 - RX4"(42.889,0.25)
  Layer 1 - Top Layer region: 40.85,0 40.85,1.4 40.939,1.4 40.939,2.6 40.739,2.6 40.739,3.725 40.939,3.725 40.939,4.925 40.539,4.925 40.539,6.035 40.939,6.035 40.939,7.235 40.389,7.235 40.389,8.33 40.939,8.33 40.939,9.53 40.238,9.53 40.238,10.615 40.939,10.615 40.939,11.815 40.238,11.815 40.238,12.9 40.939,12.9 40.939,14.1 40.389,14.1 40.389,15.195 40.939,15.195 40.939,16.395 40.539,16.395 40.539,17.505 40.939,17.505 40.939,18.705 40.739,18.705 40.739,19.83 41.239,19.83 41.239,18.705 41.039,18.705 41.039,17.505 41.438,17.505 41.438,16.395 41.039,16.395 41.039,15.195 41.588,15.195 41.588,14.1 41.039,14.1 41.039,12.9 41.739,12.9 41.739,11.815 41.039,11.815 41.039,10.615 41.739,10.615 41.739,9.53 41.039,9.53 41.039,8.33 41.588,8.33 41.588,7.235 41.039,7.235 41.039,6.035 41.438,6.035 41.438,4.925 41.039,4.925 41.039,3.725 41.239,3.725 41.239,2.6 41.039,2.6 41.039,1.4 41.127,1.4 41.127,0.885 41.367,0.885 41.367,0.608 41.127,0.608 41.127,0
  Layer 1 - Top Layer region: 43.739,0.951 43.938,0.951 43.938,20.046 43.739,20.046
  Layer 1 - Top Layer region: 41.839,0.951 42.039,0.951 42.039,20.046 41.839,20.046
  Layer 1 - Top Layer region: 39.939,0.951 40.138,0.951 40.138,20.046 39.939,20.046
  Layer 1 - Top Layer region: 38.039,0.951 38.239,0.951 38.239,20.046 38.039,20.046
  Layer 1 - Top Layer region: 36.139,0.951 36.338,0.951 36.338,20.046 36.139,20.046
  Layer 1 - Top Layer region: 5.7,0 5.7,1.4 5.789,1.4 5.789,2.6 5.589,2.6 5.589,3.725 5.789,3.725 5.789,4.925 5.389,4.925 5.389,6.035 5.789,6.035 5.789,7.235 5.239,7.235 5.239,8.33 5.789,8.33 5.789,9.53 5.089,9.53 5.089,10.615 5.789,10.615 5.789,11.815 5.089,11.815 5.089,12.9 5.789,12.9 5.789,14.1 5.239,14.1 5.239,15.195 5.789,15.195 5.789,16.395 5.389,16.395 5.389,17.505 5.789,17.505 5.789,18.705 5.589,18.705 5.589,19.83 6.089,19.83 6.089,18.705 5.889,18.705 5.889,17.505 6.289,17.505 6.289,16.395 5.889,16.395 5.889,15.195 6.439,15.195 6.439,14.1 5.889,14.1 5.889,12.9 6.589,12.9 6.589,11.815 5.889,11.815 5.889,10.615 6.589,10.615 6.589,9.53 5.889,9.53 5.889,8.33 6.439,8.33 6.439,7.235 5.889,7.235 5.889,6.035 6.289,6.035 6.289,4.925 5.889,4.925 5.889,3.725 6.089,3.725 6.089,2.6 5.889,2.6 5.889,1.4 5.977,1.4 5.977,0.885 6.217,0.885 6.217,0.608 5.977,0.608 5.977,0
  Layer 1 - Top Layer region: 3.8,0 3.8,1.4 3.889,1.4 3.889,2.6 3.689,2.6 3.689,3.725 3.889,3.725 3.889,4.925 3.489,4.925 3.489,6.035 3.889,6.035 3.889,7.235 3.339,7.235 3.339,8.33 3.889,8.33 3.889,9.53 3.189,9.53 3.189,10.615 3.889,10.615 3.889,11.815 3.189,11.815 3.189,12.9 3.889,12.9 3.889,14.1 3.339,14.1 3.339,15.195 3.889,15.195 3.889,16.395 3.489,16.395 3.489,17.505 3.889,17.505 3.889,18.705 3.689,18.705 3.689,19.83 4.189,19.83 4.189,18.705 3.989,18.705 3.989,17.505 4.389,17.505 4.389,16.395 3.989,16.395 3.989,15.195 4.538,15.195 4.538,14.1 3.989,14.1 3.989,12.9 4.689,12.9 4.689,11.815 3.989,11.815 3.989,10.615 4.689,10.615 4.689,9.53 3.989,9.53 3.989,8.33 4.538,8.33 4.538,7.235 3.989,7.235 3.989,6.035 4.389,6.035 4.389,4.925 3.989,4.925 3.989,3.725 4.189,3.725 4.189,2.6 3.989,2.6 3.989,1.4 4.077,1.4 4.077,0.885 4.317,0.885 4.317,0.608 4.077,0.608 4.077,0
  Layer 1 - Top Layer region: 0,0 0,1.4 0.089,1.4 0.089,2.6 -0.111,2.6 -0.111,3.725 0.089,3.725 0.089,4.925 -0.311,4.925 -0.311,6.035 0.089,6.035 0.089,7.235 -0.461,7.235 -0.461,8.33 0.089,8.33 0.089,9.53 -0.611,9.53 -0.611,10.615 0.089,10.615 0.089,11.815 -0.611,11.815 -0.611,12.9 0.089,12.9 0.089,14.1 -0.461,14.1 -0.461,15.195 0.089,15.195 0.089,16.395 -0.311,16.395 -0.311,17.505 0.089,17.505 0.089,18.705 -0.111,18.705 -0.111,19.83 0.389,19.83 0.389,18.705 0.189,18.705 0.189,17.505 0.589,17.505 0.589,16.395 0.189,16.395 0.189,15.195 0.738,15.195 0.738,14.1 0.189,14.1 0.189,12.9 0.889,12.9 0.889,11.815 0.189,11.815 0.189,10.615 0.889,10.615 0.889,9.53 0.189,9.53 0.189,8.33 0.738,8.33 0.738,7.235 0.189,7.235 0.189,6.035 0.589,6.035 0.589,4.925 0.189,4.925 0.189,3.725 0.389,3.725 0.389,2.6 0.189,2.6 0.189,1.4 0.277,1.4 0.277,0.885 0.517,0.885 0.517,0.608 0.277,0.608 0.277,0
  Layer 1 - Top Layer region: 37.05,0 37.05,1.4 37.139,1.4 37.139,2.6 36.939,2.6 36.939,3.725 37.139,3.725 37.139,4.925 36.739,4.925 36.739,6.035 37.139,6.035 37.139,7.235 36.589,7.235 36.589,8.33 37.139,8.33 37.139,9.53 36.438,9.53 36.438,10.615 37.139,10.615 37.139,11.815 36.438,11.815 36.438,12.9 37.139,12.9 37.139,14.1 36.589,14.1 36.589,15.195 37.139,15.195 37.139,16.395 36.739,16.395 36.739,17.505 37.139,17.505 37.139,18.705 36.939,18.705 36.939,19.83 37.439,19.83 37.439,18.705 37.239,18.705 37.239,17.505 37.638,17.505 37.638,16.395 37.239,16.395 37.239,15.195 37.788,15.195 37.788,14.1 37.239,14.1 37.239,12.9 37.939,12.9 37.939,11.815 37.239,11.815 37.239,10.615 37.939,10.615 37.939,9.53 37.239,9.53 37.239,8.33 37.788,8.33 37.788,7.235 37.239,7.235 37.239,6.035 37.638,6.035 37.638,4.925 37.239,4.925 37.239,3.725 37.439,3.725 37.439,2.6 37.239,2.6 37.239,1.4 37.327,1.4 37.327,0.885 37.567,0.885 37.567,0.608 37.327,0.608 37.327,0
  Layer 1 - Top Layer region: 38.95,0 38.95,1.4 39.039,1.4 39.039,2.6 38.839,2.6 38.839,3.725 39.039,3.725 39.039,4.925 38.639,4.925 38.639,6.035 39.039,6.035 39.039,7.235 38.489,7.235 38.489,8.33 39.039,8.33 39.039,9.53 38.339,9.53 38.339,10.615 39.039,10.615 39.039,11.815 38.339,11.815 38.339,12.9 39.039,12.9 39.039,14.1 38.489,14.1 38.489,15.195 39.039,15.195 39.039,16.395 38.639,16.395 38.639,17.505 39.039,17.505 39.039,18.705 38.839,18.705 38.839,19.83 39.339,19.83 39.339,18.705 39.139,18.705 39.139,17.505 39.539,17.505 39.539,16.395 39.139,16.395 39.139,15.195 39.689,15.195 39.689,14.1 39.139,14.1 39.139,12.9 39.839,12.9 39.839,11.815 39.139,11.815 39.139,10.615 39.839,10.615 39.839,9.53 39.139,9.53 39.139,8.33 39.689,8.33 39.689,7.235 39.139,7.235 39.139,6.035 39.539,6.035 39.539,4.925 39.139,4.925 39.139,3.725 39.339,3.725 39.339,2.6 39.139,2.6 39.139,1.4 39.227,1.4 39.227,0.885 39.467,0.885 39.467,0.608 39.227,0.608 39.227,0
  Layer 1 - Top Layer region: 42.75,0 42.75,1.4 42.839,1.4 42.839,2.6 42.639,2.6 42.639,3.725 42.839,3.725 42.839,4.925 42.439,4.925 42.439,6.035 42.839,6.035 42.839,7.235 42.289,7.235 42.289,8.33 42.839,8.33 42.839,9.53 42.139,9.53 42.139,10.615 42.839,10.615 42.839,11.815 42.139,11.815 42.139,12.9 42.839,12.9 42.839,14.1 42.289,14.1 42.289,15.195 42.839,15.195 42.839,16.395 42.439,16.395 42.439,17.505 42.839,17.505 42.839,18.705 42.639,18.705 42.639,19.83 43.139,19.83 43.139,18.705 42.939,18.705 42.939,17.505 43.339,17.505 43.339,16.395 42.939,16.395 42.939,15.195 43.489,15.195 43.489,14.1 42.939,14.1 42.939,12.9 43.639,12.9 43.639,11.815 42.939,11.815 42.939,10.615 43.639,10.615 43.639,9.53 42.939,9.53 42.939,8.33 43.489,8.33 43.489,7.235 42.939,7.235 42.939,6.035 43.339,6.035 43.339,4.925 42.939,4.925 42.939,3.725 43.139,3.725 43.139,2.6 42.939,2.6 42.939,1.4 43.027,1.4 43.027,0.885 43.267,0.885 43.267,0.608 43.027,0.608 43.027,0
  Layer 1 - Top Layer region: 1.9,0 1.9,1.4 1.989,1.4 1.989,2.6 1.789,2.6 1.789,3.725 1.989,3.725 1.989,4.925 1.589,4.925 1.589,6.035 1.989,6.035 1.989,7.235 1.439,7.235 1.439,8.33 1.989,8.33 1.989,9.53 1.289,9.53 1.289,10.615 1.989,10.615 1.989,11.815 1.289,11.815 1.289,12.9 1.989,12.9 1.989,14.1 1.439,14.1 1.439,15.195 1.989,15.195 1.989,16.395 1.589,16.395 1.589,17.505 1.989,17.505 1.989,18.705 1.789,18.705 1.789,19.83 2.289,19.83 2.289,18.705 2.089,18.705 2.089,17.505 2.489,17.505 2.489,16.395 2.089,16.395 2.089,15.195 2.639,15.195 2.639,14.1 2.089,14.1 2.089,12.9 2.789,12.9 2.789,11.815 2.089,11.815 2.089,10.615 2.789,10.615 2.789,9.53 2.089,9.53 2.089,8.33 2.639,8.33 2.639,7.235 2.089,7.235 2.089,6.035 2.489,6.035 2.489,4.925 2.089,4.925 2.089,3.725 2.289,3.725 2.289,2.6 2.089,2.6 2.089,1.4 2.177,1.4 2.177,0.885 2.417,0.885 2.417,0.608 2.177,0.608 2.177,0
  Layer 1 - Top Layer region: -0.911,0.951 -0.711,0.951 -0.711,20.046 -0.911,20.046
  Layer 1 - Top Layer region: 0.989,0.951 1.189,0.951 1.189,20.046 0.989,20.046
  Layer 1 - Top Layer region: 2.889,0.951 3.089,0.951 3.089,20.046 2.889,20.046
  Layer 1 - Top Layer region: 4.789,0.951 4.989,0.951 4.989,20.046 4.789,20.046
  Layer 1 - Top Layer region: 6.689,0.951 6.889,0.951 6.889,20.046 6.689,20.046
